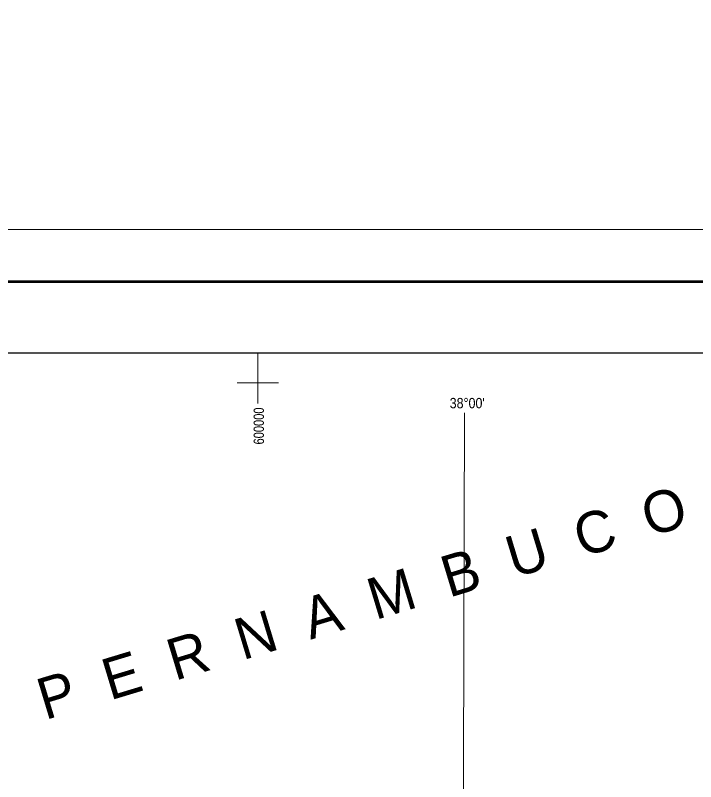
# Model space of a CAD drawing. Extents: x -1643653 to 4543381, y 1624270 to 13878484.
# Drawn here: x 588293 to 621123, y 9005760 to 9042726 of the extents above; entities that cross this region are included whole.
import ezdxf
from ezdxf.enums import TextEntityAlignment as Align

# ---------------------------------------------------------------- set-up
doc = ezdxf.new("R2010")
doc.units = 0
doc.header["$LTSCALE"] = 200
for name, color, linetype, lineweight in [('1', 7, 'Continuous', 13), ('2', 7, 'Continuous', 13), ('3', 7, 'Continuous', 13), ('60', 7, 'Continuous', 13)]:
    doc.layers.add(name, color=color, linetype=linetype, lineweight=lineweight)
for name, color, linetype in [('42', 7, 'Continuous'), ('46', 7, 'Continuous'), ('47', 7, 'Continuous')]:
    doc.layers.add(name, color=color, linetype=linetype)

msp = doc.modelspace()

# ---------------------------------------------------------------- linework, layer by layer
at = {"layer": '1'}
msp.add_lwpolyline([(609971.9, 9023551.8), (609764.7, 8949706.7), (609734.2, 8939404.4)], dxfattribs=at)
at = {"layer": '2'}
for p, q in [((600000, 9024000), (600000, 9026438.8)), ((599000, 9025000), (601000, 9025000))]:
    msp.add_line(p, q, dxfattribs=at)
at = {"layer": '3'}
msp.add_lwpolyline([(842807.3, 9032387.8), (842807.3, 8883887.8), (553961.7, 8883887.8), (553961.7, 9032387.8)], close=True, dxfattribs=at)
at = {"layer": '3', "lineweight": 53}
msp.add_lwpolyline([(840307.3, 9029887.8), (840307.3, 8886387.8), (560211.7, 8886387.8), (560211.7, 9029887.8)], close=True, dxfattribs=at)
at = {"layer": '3', "lineweight": 25}
msp.add_lwpolyline([(563033.9, 9026438.8), (793061.1, 9026438.8), (793495.6, 8889836.8), (563468.3, 8889836.8)], close=True, dxfattribs=at)
at = {"layer": '60', "lineweight": 25}
msp.add_spline([(814781, 9009175.5), (814787.2, 9009173.4), (814796.9, 9009173.4), (814799.4, 9009172.4), (814805.1, 9009174.5), (814805.6, 9009176.5), (814811.7, 9009179.5), (814811.7, 9009179.5), (814801.5, 9009181), (814790.7, 9009181.5), (814784.1, 9009183.1), (814777.4, 9009185.1), (814778.4, 9009175.5)], degree=3, dxfattribs=at)

# ---------------------------------------------------------------- texts
at = {"layer": '42'}
msp.add_text('P  E  R  N  A  M  B  U  C  O', height=2000, rotation=16.855, dxfattribs=at).set_placement((589730.9, 9008723.5))
at = {"layer": '46', "width": 0.9}
msp.add_text("38°00'", height=500, dxfattribs=at).set_placement((610099.9, 9023770.4), align=Align.CENTER)
at = {"layer": '47', "width": 0.8}
msp.add_text('600000', height=500, rotation=90, dxfattribs=at).set_placement((600290.6, 9022917.4), align=Align.CENTER)

doc.saveas('drawing.dxf')
